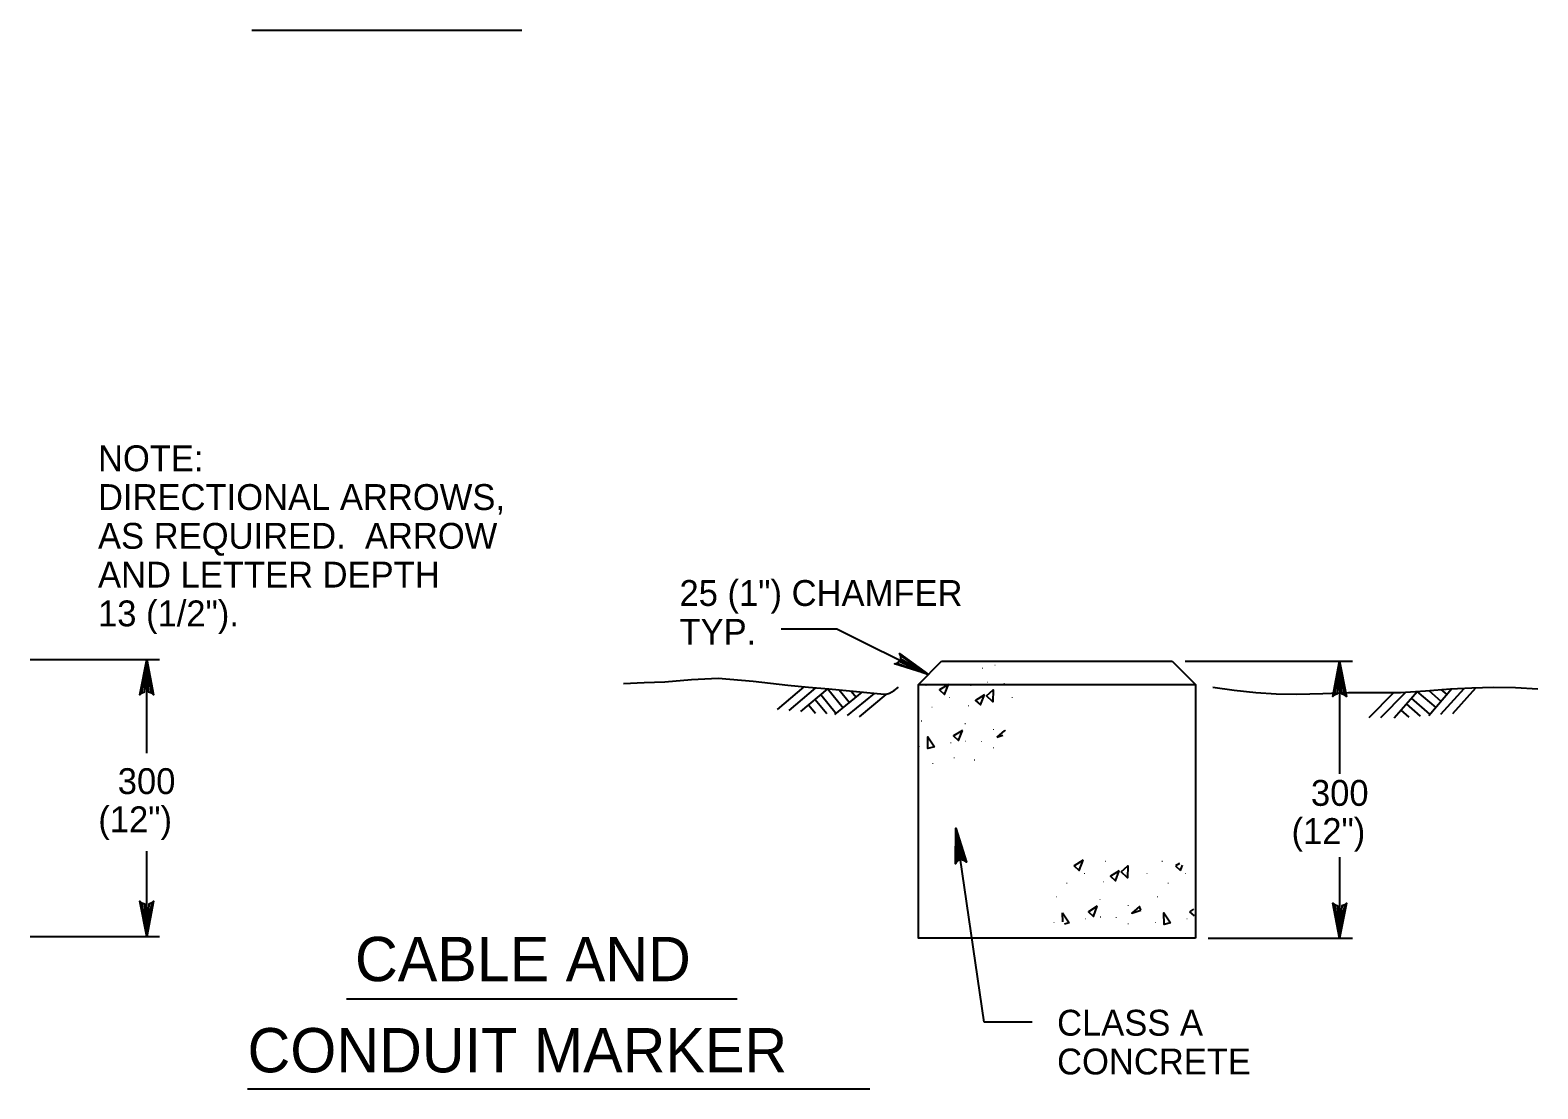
# Model space of a CAD drawing. Extents: x 638448 to 639352, y 297825 to 299013.
# Drawn here: x 638573.5 to 638769.6, y 297977.3 to 298114.9 of the extents above; entities that cross this region are included whole.
import ezdxf

# ---------------------------------------------------------------- set-up
doc = ezdxf.new("R2010")
doc.units = 0
doc.layers.add('2', color=7, linetype='Continuous')
doc.layers.add('3', color=7, linetype='Continuous')

msp = doc.modelspace()

# ---------------------------------------------------------------- linework, layer by layer
at = {"layer": '2'}
for p, q in [((638573.51, 298033.11), (638590.34, 298033.11)), ((638588.66, 298020.92), (638588.66, 298033.11)), ((638689.02, 298029.88), (638692.02, 298032.88)), ((638722.02, 298032.88), (638725.02, 298029.88)), ((638723.7, 298032.88), (638745.46, 298032.88)), ((638743.78, 298032.88), (638743.78, 298018.24)), ((638670.69, 298026.63), (638674.17, 298029.56)), ((638672.19, 298026.5), (638675.69, 298029.44)), ((638673.74, 298026.37), (638677.24, 298029.31)), ((638676.31, 298028.55), (638678.31, 298026.11)), ((638677.17, 298029.32), (638679.21, 298026.82)), ((638678.16, 298025.97), (638681.71, 298028.88)), ((638678.71, 298029.16), (638680.05, 298027.54)), ((638679.8, 298025.81), (638683.29, 298028.69)), ((638680.28, 298029.01), (638680.92, 298028.23)), ((638681.35, 298025.66), (638684.83, 298028.54)), ((638747.62, 298025.58), (638750.82, 298028.81)), ((638749.12, 298025.59), (638752.34, 298028.83)), ((638750.88, 298025.54), (638753.89, 298028.98)), ((638753.82, 298028.96), (638756.27, 298026.86)), ((638755.37, 298025.84), (638758.37, 298029.33)), ((638755.37, 298029.08), (638756.96, 298027.71)), ((638756.93, 298026), (638759.96, 298029.35)), ((638756.94, 298029.2), (638757.7, 298028.55)), ((638758.48, 298026.08), (638761.51, 298029.43)), ((638674.73, 298027.2), (638675.61, 298026.15)), ((638675.57, 298027.91), (638677.11, 298026.07)), ((638751.73, 298026.51), (638752.76, 298025.61)), ((638752.45, 298027.34), (638754.26, 298025.76)), ((638753.1, 298028.08), (638755.47, 298026)), ((638697.54, 297985.99), (638693.86, 298011.2)), ((638588.66, 297997.11), (638588.66, 298008.2)), ((638743.78, 298007.42), (638743.78, 297996.88)), ((638573.51, 297997.11), (638590.34, 297997.11)), ((638726.7, 297996.88), (638745.46, 297996.88)), ((638703.79, 297985.99), (638697.54, 297985.99))]:
    msp.add_line(p, q, dxfattribs=at)
for points in [[(638671.15, 298037.09), (638678.38, 298037.09), (638690.32, 298031.18)], [(638588, 298028.75), (638588.38, 298028.92), (638588.66, 298033.11), (638588, 298028.75), (638587.77, 298028.53), (638588.66, 298033.11), (638588.91, 298028.92), (638589.28, 298028.77), (638588.66, 298033.11), (638589.53, 298028.53), (638589.28, 298028.77)], [(638686.66, 298033.61), (638686.67, 298033.25), (638690.32, 298031.18), (638686.66, 298033.61), (638686.55, 298033.88), (638690.32, 298031.18), (638686.47, 298032.86), (638686.2, 298032.65), (638690.32, 298031.18), (638685.89, 298032.56), (638686.2, 298032.65)], [(638692.02, 298032.88), (638722.02, 298032.88)], [(638697, 298032.82), (638696.98, 298032.89)], [(638697.04, 298032.89), (638697, 298032.82)], [(638743.13, 298028.52), (638743.51, 298028.68), (638743.78, 298032.88), (638743.13, 298028.52), (638742.9, 298028.3), (638743.78, 298032.88), (638744.03, 298028.69), (638744.41, 298028.53), (638743.78, 298032.88), (638744.66, 298028.3), (638744.41, 298028.53)], [(638650.68, 298029.99), (638653.35, 298030.1), (638656.02, 298030.22), (638659.5, 298030.53), (638662.98, 298030.69), (638667.51, 298030.28), (638672.04, 298029.76), (638674.71, 298029.53), (638677.38, 298029.3), (638680.98, 298028.94), (638684.57, 298028.6), (638684.83, 298028.6), (638685.25, 298028.72), (638685.86, 298029.07), (638686.43, 298029.53)], [(638689.02, 298029.88), (638725.02, 298029.88)], [(638725.02, 297996.88), (638689.02, 297996.88), (638689.02, 298029.88)], [(638725.02, 298029.88), (638725.02, 297996.88)], [(638727.3, 298029.53), (638730.08, 298029.12), (638732.87, 298028.83), (638735.54, 298028.65), (638738.21, 298028.6), (638741.58, 298028.71), (638744.94, 298028.83), (638748.31, 298028.81), (638751.68, 298028.83), (638754.93, 298029.05), (638758.18, 298029.3), (638760.96, 298029.44), (638763.75, 298029.53), (638766.65, 298029.48), (638769.55, 298029.3)], [(638700.21, 298023.87), (638699.22, 298023.01)], [(638699.22, 298023.01), (638700, 298023.27)], [(638700.27, 298023.74), (638700.21, 298023.87)], [(638693.97, 298006.81), (638694.26, 298007.01), (638693.86, 298011.2), (638693.97, 298006.81), (638693.82, 298006.56), (638693.86, 298011.2), (638694.69, 298007.08), (638695.02, 298006.98), (638693.86, 298011.2), (638695.27, 298006.78), (638695.02, 298006.98)], [(638722.97, 298006.61), (638722.45, 298006.29)], [(638722.45, 298006.29), (638723.11, 298005.7)], [(638723.11, 298005.7), (638723.36, 298006.36)], [(638589.31, 298001.47), (638588.93, 298001.31), (638588.66, 297997.11), (638589.31, 298001.47), (638589.54, 298001.69), (638588.66, 297997.11), (638588.41, 298001.3), (638588.03, 298001.46), (638588.66, 297997.11), (638587.78, 298001.69), (638588.03, 298001.46)], [(638744.44, 298001.24), (638744.06, 298001.08), (638743.78, 297996.88), (638744.44, 298001.24), (638744.67, 298001.46), (638743.78, 297996.88), (638743.53, 298001.07), (638743.16, 298001.23), (638743.78, 297996.88), (638742.91, 298001.46), (638743.16, 298001.23)], [(638707.77, 297999.02), (638707.75, 298000.2)], [(638707.75, 298000.2), (638708.61, 297998.87)], [(638724.8, 298000.64), (638724.28, 298000.31)], [(638724.28, 298000.31), (638724.85, 297999.79)], [(638708.61, 297998.87), (638708.02, 297998.73)]]:
    msp.add_lwpolyline(points, dxfattribs=at)
for points in [[(638692.9, 298029.88), (638691.75, 298029.16), (638692.4, 298028.57)], [(638697.6, 298028.52), (638696.45, 298027.8), (638697.1, 298027.22)], [(638697.85, 298028.4), (638698.71, 298029.15), (638698.67, 298027.59)], [(638691.08, 298021.74), (638690.24, 298021.54), (638690.22, 298023.07)], [(638694.73, 298023.9), (638693.58, 298023.18), (638694.23, 298022.59)], [(638710.43, 298007.01), (638709.28, 298006.29), (638709.93, 298005.7)], [(638715.13, 298005.65), (638713.98, 298004.93), (638714.63, 298004.35)], [(638715.38, 298005.53), (638716.24, 298006.28), (638716.2, 298004.72)], [(638712.26, 298001.03), (638711.11, 298000.31), (638711.76, 297999.72)], [(638717.94, 298000.54), (638717.74, 298001), (638716.75, 298000.14)], [(638721.78, 297998.87), (638720.95, 297998.67), (638720.92, 298000.2)]]:
    msp.add_lwpolyline(points, close=True, dxfattribs=at)
at = {"layer": '3'}
for p, q in [((638602.34, 298114.9), (638637.44, 298114.9)), ((638614.63, 297988.99), (638665.43, 297988.99)), ((638601.76, 297977.31), (638682.69, 297977.31))]:
    msp.add_line(p, q, dxfattribs=at)

# ---------------------------------------------------------------- texts
at = {"layer": '2'}
for p in [(638698.81, 298032.31), (638697.19, 298031.91), (638689.83, 298029.68), (638695.67, 298029.68), (638697.81, 298030.11), (638699.99, 298029.9), (638690.61, 298026.84), (638692.9, 298028.09), (638695.36, 298027.01), (638701.04, 298028.09), (638689.24, 298025.05), (638694.92, 298024.7), (638694.99, 298022.44), (638697.02, 298022.38), (638698.6, 298023.93), (638688.95, 298021.72), (638693.06, 298022.22), (638698.6, 298021.55), (638690.72, 298019.51), (638693.49, 298020.26), (638696.13, 298019.98), (638713.2, 298006.81), (638720.53, 298006.81), (638710.43, 298005.22), (638718.57, 298005.22), (638723.6, 298005.22), (638708.14, 298003.97), (638712.89, 298004.14), (638721.31, 298003.97), (638706.77, 298002.18), (638712.45, 298001.83), (638716.13, 298001.06), (638719.94, 298002.18), (638706.48, 297998.85), (638710.59, 297999.35), (638712.52, 297999.57), (638714.55, 297999.51), (638719.65, 297998.85), (638723.76, 297999.35), (638716.13, 297998.68)]:
    msp.add_text('.', height=0.893, dxfattribs=at).set_placement(p)
at = {"layer": '3'}
for s, height, p in [('NOTE:', 3.36, (638582.33, 298057.58)), ('DIRECTIONAL ARROWS,', 3.36, (638582.33, 298052.54)), ('AS REQUIRED.  ARROW', 3.36, (638582.33, 298047.5)), ('AND LETTER DEPTH', 3.36, (638582.33, 298042.46)), ('25 (1") CHAMFER', 3.36, (638657.94, 298040.07)), ('13 (1/2").', 3.36, (638582.33, 298037.42)), ('TYP.', 3.36, (638657.94, 298035.03)), ('300', 3.36, (638584.9, 298015.62)), ('300', 3.36, (638740.05, 298014.09)), ('(12")', 3.36, (638582.37, 298010.66)), ('(12")', 3.36, (638737.53, 298009.13)), ('CABLE AND', 5.76, (638615.75, 297991.3)), ('CLASS A', 3.36, (638707.04, 297984.22)), ('CONDUIT MARKER', 5.76, (638601.77, 297979.45)), ('CONCRETE', 3.36, (638707.04, 297979.18))]:
    msp.add_text(s, height=height, dxfattribs=at).set_placement(p)

doc.saveas('drawing.dxf')
